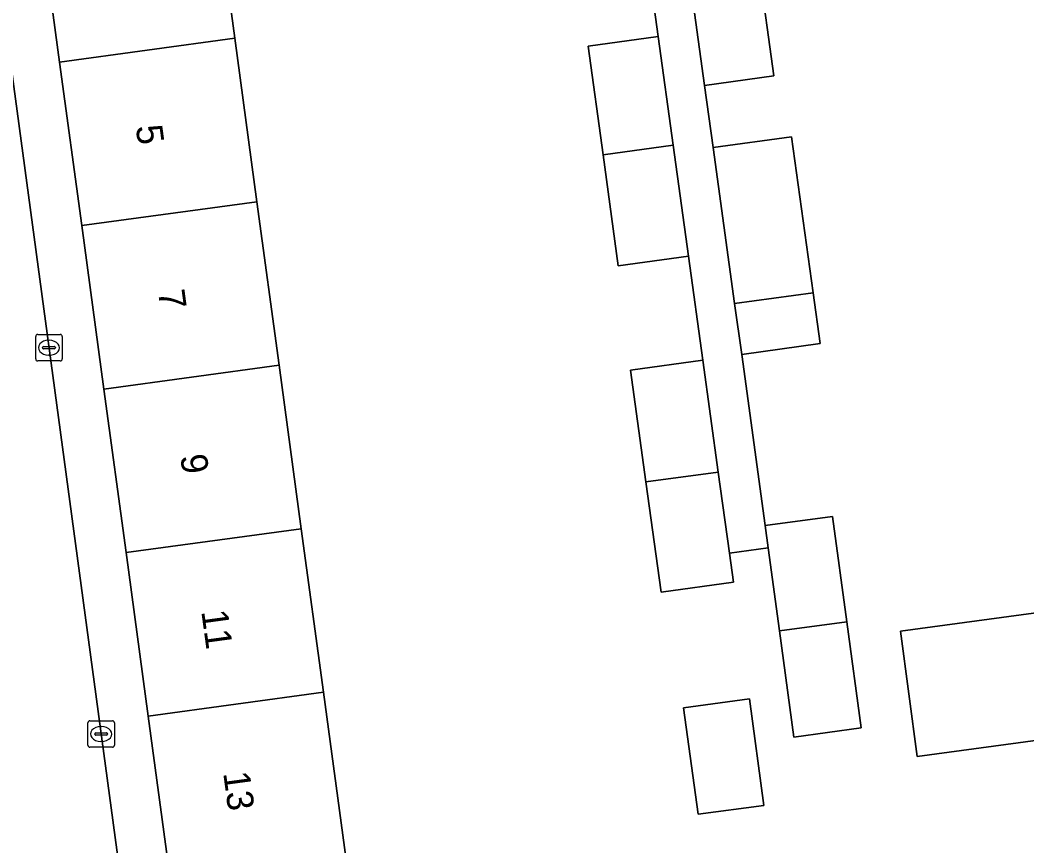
# Model space of a CAD drawing. Extents: x 159053 to 160042, y 380449 to 381423.
# Drawn here: x 159553.7 to 159591.74, y 380924.73 to 380955.93 of the extents above; entities that cross this region are included whole.
import ezdxf

# ---------------------------------------------------------------- set-up
doc = ezdxf.new("R2010")
doc.units = 0
for name, color, linetype in [('IMGEO_Erf', 7, 'Continuous'), ('IMGEO_Kolk', 7, 'Continuous'), ('IMGEO_Pand', 7, 'Continuous'), ('IMGEO_Pand_nummerreeks', 7, 'Continuous'), ('IMGEO_Rijbaan_lokaal_open', 7, 'Continuous'), ('IMGEO_Voetpad_open', 7, 'Continuous')]:
    doc.layers.add(name, color=color, linetype=linetype)

msp = doc.modelspace()

# ---------------------------------------------------------------- linework, layer by layer
at = {"layer": 'IMGEO_Erf'}
for points in [[(159560.979, 380961.426), (159561.815, 380955.248), (159562.651, 380949.069), (159563.488, 380942.89), (159564.324, 380936.711), (159565.16, 380930.533), (159566.016, 380924.203)], [(159581.616, 380957.945), (159582.173, 380953.826), (159579.56, 380953.465), (159579.884, 380951.119), (159582.846, 380951.528), (159583.661, 380945.625), (159583.925, 380943.711), (159580.962, 380943.302), (159581.855, 380936.832), (159584.393, 380937.175), (159584.931, 380933.199), (159585.473, 380929.188), (159582.936, 380928.845), (159582.393, 380932.856), (159581.968, 380935.998), (159580.497, 380935.796), (159580.649, 380934.694), (159577.921, 380934.319), (159577.347, 380938.482), (159576.764, 380942.712), (159579.493, 380943.088), (159578.951, 380947.02), (159576.302, 380946.655), (159575.724, 380950.847), (159575.159, 380954.954), (159577.808, 380955.319), (159577.242, 380959.429)], [(159598.854, 380929.631), (159587.597, 380928.108), (159586.956, 380932.845), (159598.213, 380934.368)]]:
    msp.add_lwpolyline(points, dxfattribs=at)
msp.add_lwpolyline([(159581.801, 380926.26), (159579.312, 380925.924), (159578.768, 380929.946), (159581.257, 380930.282)], close=True, dxfattribs=at)
at = {"layer": 'IMGEO_Kolk'}
for p, q in [((159554.293, 380943.129), (159554.293, 380943.981)), ((159554.368, 380944.055), (159555.22, 380944.055)), ((159555.294, 380943.981), (159555.294, 380943.129)), ((159554.595, 380943.598), (159554.993, 380943.598)), ((159554.781, 380943.835), (159554.806, 380943.835)), ((159554.552, 380943.549), (159554.552, 380943.561)), ((159554.99, 380943.512), (159554.592, 380943.512)), ((159554.804, 380943.275), (159554.779, 380943.275)), ((159555.036, 380943.561), (159555.036, 380943.549)), ((159555.22, 380943.055), (159554.368, 380943.055)), ((159556.264, 380928.532), (159556.264, 380929.384)), ((159556.339, 380929.458), (159557.191, 380929.458)), ((159556.752, 380929.238), (159556.777, 380929.238)), ((159557.265, 380929.384), (159557.265, 380928.532)), ((159556.523, 380928.952), (159556.523, 380928.964)), ((159556.961, 380928.915), (159556.563, 380928.915)), ((159556.566, 380929.001), (159556.964, 380929.001)), ((159557.007, 380928.964), (159557.007, 380928.952)), ((159557.191, 380928.458), (159556.339, 380928.458)), ((159556.775, 380928.678), (159556.75, 380928.678))]:
    msp.add_line(p, q, dxfattribs=at)
for points in [[(159554.293, 380943.129), (159554.293, 380943.981)], [(159554.368, 380944.055), (159555.22, 380944.055)], [(159555.294, 380943.981), (159555.294, 380943.129)], [(159555.22, 380943.055), (159554.368, 380943.055)], [(159556.264, 380928.532), (159556.264, 380929.384)], [(159556.339, 380929.458), (159557.191, 380929.458)], [(159557.265, 380929.384), (159557.265, 380928.532)], [(159557.191, 380928.458), (159556.339, 380928.458)]]:
    msp.add_lwpolyline(points, dxfattribs=at)
for centre, radius, start, end in [((159554.37, 380943.979), 0.0765, 91.552, 178.448), ((159554.37, 380943.979), 0.0765, 91.552, 178.448), ((159555.218, 380943.979), 0.0765, 1.552, 88.448), ((159555.218, 380943.979), 0.0765, 1.552, 88.448), ((159554.592, 380943.558), 0.0403, 85.8775, 175.7526), ((159554.997, 380943.56), 0.0386, 1.7309, 96.639), ((159554.589, 380943.548), 0.0366, 178.938, 274.7102), ((159554.993, 380943.555), 0.043, 264.8664, 352.4533), ((159554.37, 380943.131), 0.0765, 181.552, 268.448), ((159554.37, 380943.131), 0.0765, 181.552, 268.448), ((159555.218, 380943.131), 0.0765, 271.552, 358.448), ((159555.218, 380943.131), 0.0765, 271.552, 358.448), ((159556.341, 380929.382), 0.0765, 91.552, 178.448), ((159556.341, 380929.382), 0.0765, 91.552, 178.448), ((159557.189, 380929.382), 0.0765, 1.552, 88.448), ((159557.189, 380929.382), 0.0765, 1.552, 88.448), ((159556.563, 380928.961), 0.0403, 85.8775, 175.7526), ((159556.56, 380928.951), 0.0366, 178.938, 274.7102), ((159556.964, 380928.958), 0.043, 264.8664, 352.4533), ((159556.968, 380928.963), 0.0386, 1.7309, 96.639), ((159556.341, 380928.534), 0.0765, 181.552, 268.448), ((159556.341, 380928.534), 0.0765, 181.552, 268.448), ((159557.189, 380928.534), 0.0765, 271.552, 358.448), ((159557.189, 380928.534), 0.0765, 271.552, 358.448)]:
    msp.add_arc(centre, radius, start, end, dxfattribs=at)
for centre, major_axis, ratio, start_param, end_param in [((159554.78, 380943.555), (-0.387, 0.002), 0.722429, 4.712389, 7.853982), ((159554.805, 380943.555), (-0.39, 0.002), 0.717154, 1.570796, 4.712389), ((159556.751, 380928.958), (-0.387, 0.002), 0.722429, 4.712389, 7.853982), ((159556.776, 380928.958), (-0.39, 0.002), 0.717154, 1.570796, 4.712389)]:
    msp.add_ellipse(centre, major_axis=major_axis, ratio=ratio, start_param=start_param, end_param=end_param, dxfattribs=at)
at = {"layer": 'IMGEO_Pand'}
for points in [[(159555.196, 380954.348), (159561.815, 380955.248), (159560.979, 380961.426), (159554.36, 380960.526)], [(159581.616, 380957.945), (159578.991, 380957.59), (159579.56, 380953.465), (159582.173, 380953.826)], [(159555.196, 380954.348), (159556.032, 380948.169), (159562.651, 380949.069), (159561.815, 380955.248)], [(159575.724, 380950.847), (159578.374, 380951.207), (159577.808, 380955.319), (159575.159, 380954.954)], [(159575.724, 380950.847), (159576.302, 380946.655), (159578.951, 380947.02), (159578.374, 380951.207)], [(159580.697, 380945.224), (159583.661, 380945.625), (159582.846, 380951.528), (159579.884, 380951.119)], [(159562.651, 380949.069), (159556.032, 380948.169), (159556.868, 380941.99), (159563.488, 380942.89)], [(159580.697, 380945.224), (159580.962, 380943.302), (159583.925, 380943.711), (159583.661, 380945.625)], [(159563.488, 380942.89), (159556.868, 380941.99), (159557.704, 380935.811), (159564.324, 380936.711)], [(159577.347, 380938.482), (159580.076, 380938.853), (159579.493, 380943.088), (159576.764, 380942.712)], [(159580.076, 380938.853), (159577.347, 380938.482), (159577.921, 380934.319), (159580.649, 380934.694), (159580.497, 380935.796)], [(159584.393, 380937.175), (159581.855, 380936.832), (159581.968, 380935.998), (159582.393, 380932.856), (159584.931, 380933.199)], [(159564.324, 380936.711), (159557.704, 380935.811), (159558.54, 380929.633), (159565.16, 380930.533)], [(159604.781, 380935.885), (159598.13, 380934.985), (159598.213, 380934.368), (159586.956, 380932.845), (159587.597, 380928.108), (159598.854, 380929.631), (159598.987, 380928.65), (159605.638, 380929.55)], [(159582.393, 380932.856), (159582.936, 380928.845), (159585.473, 380929.188), (159584.931, 380933.199)], [(159565.16, 380930.533), (159558.54, 380929.633), (159559.396, 380923.307), (159566.016, 380924.203)], [(159579.312, 380925.924), (159581.801, 380926.26), (159581.257, 380930.282), (159578.768, 380929.946)]]:
    msp.add_lwpolyline(points, close=True, dxfattribs=at)
at = {"layer": 'IMGEO_Rijbaan_lokaal_open'}
msp.add_lwpolyline([(159523.623, 380963.67), (159540.399, 380917.466), (159544.525, 380918.985), (159545.92, 380915.197), (159554.315, 380916.905), (159553.779, 380920.87), (159557.786, 380921.412), (159551.745, 380966.134), (159548.264, 380965.623), (159549.182, 380958.96), (159552.427, 380935.06), (159552.712, 380932.815)], dxfattribs=at)
at = {"layer": 'IMGEO_Voetpad_open'}
for points in [[(159579.56, 380953.465), (159578.991, 380957.59), (159578.129, 380963.91), (159577.607, 380967.619), (159577.269, 380970.116), (159575.804, 380969.914), (159576.138, 380967.442), (159576.675, 380963.544), (159577.242, 380959.429), (159577.808, 380955.319), (159578.374, 380951.207), (159578.951, 380947.02), (159579.493, 380943.088), (159580.076, 380938.853), (159580.497, 380935.796), (159581.968, 380935.998), (159581.855, 380936.832), (159580.962, 380943.302), (159580.697, 380945.224), (159579.884, 380951.119)], [(159557.704, 380935.811), (159556.868, 380941.99), (159556.032, 380948.169), (159555.196, 380954.348), (159554.36, 380960.526), (159553.503, 380966.86), (159551.678, 380966.63), (159551.745, 380966.134), (159557.786, 380921.412), (159559.619, 380921.66), (159559.396, 380923.307), (159558.54, 380929.633)]]:
    msp.add_lwpolyline(points, close=True, dxfattribs=at)

# ---------------------------------------------------------------- texts
at = {"layer": 'IMGEO_Pand_nummerreeks'}
for s, p in [('5', (159558.068, 380951.916)), ('7', (159558.91, 380945.694)), ('9', (159559.752, 380939.472)), ('11', (159560.547, 380933.594)), ('13', (159561.374, 380927.485))]:
    msp.add_text(s, height=1, rotation=277.7057, dxfattribs=at).set_placement(p)

doc.saveas('drawing.dxf')
